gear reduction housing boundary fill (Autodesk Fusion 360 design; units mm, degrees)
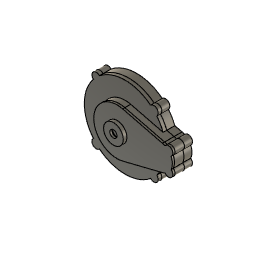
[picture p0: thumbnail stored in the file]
parameter "Drive_Gear_Dia" = 96 (= "( Drive_Gear_Teeth * Gear_Module ) * 1 mm")
parameter "Driven_Gear_Dia" = 32 (= "( Driven_Gear_Teeth * Gear_Module ) * 1 mm")
parameter "Idle_Gear_Dia" = 20 (= "( Idle_Gear_Teeth * Gear_Module ) * 1 mm")
parameter "Mount_Bolts" = 8
parameter "Mount_Bolt_Flange" = 12
parameter "Idle_Gear_Shaft" = 8
parameter "Gear_Clearance_Dia" = 8
parameter "Drive_Gear_Shaft" = 10
parameter "Idle_Gear_Thickness" = 21
parameter "Gear_Thickness" = 8
parameter "Housing_Wall_Thickness" = 3
parameter "Gear_Gap" = 5
sketch "Layout Sketch" plane through (0, 0, 0) normal (0, 1, 0) x axis (1, 0, 0)
  circle C1 centre (0, 0) radius 48
  circle C2 centre (0, 0) radius 16
  circle C3 centre (58, 0) radius 10
  circle C4 centre (22.6316, -12.7989) radius 10
  circle C5 centre (38, 0) radius 10
  point P1 (0, 0)
  point P2 (0, 0)
  point P3 (0, 0)
  point P4 (58, 0)
  coincident P1 P2
  concentric C1 C2
  horizontal P3 P4
  tangent C1 C3
  tangent C3 C5
  tangent C4 C5
  tangent C2 C4
  tangent C1 C5
  dimension "d12" diameter C1 = 96 (= "Drive_Gear_Dia")
  dimension "d13" diameter C2 = 32 (= "Driven_Gear_Dia")
  dimension "d14" diameter C3 = 20 (= "Idle_Gear_Dia")
  dimension "d15" diameter C4 = 20 (= "Idle_Gear_Dia")
  dimension "d16" diameter C5 = 20 (= "Idle_Gear_Dia")
sketch "Housing Layout Sketch" plane through (0, 0, 0) normal (0, 1, 0) x axis (1, 0, 0)
  line L1 (0, 56) -> (0, 0)
  line L2 (39.598, 39.598) -> (0, 0)
  line L3 (-56, 0) -> (0, 0)
  line L4 (70.7279, -12.7279) -> (58, 0)
  line L5 (62.3448, -17.4678) -> (7.7241, -31.0538)
  line L6 (62.3448, 17.4678) -> (7.7241, 31.0538)
  circle C1 centre (0, 0) radius 56
  circle C2 centre (0, 0) radius 48
  circle C3 centre (58, 0) radius 10
  circle C4 centre (58, 0) radius 18
  circle C5 centre (39.598, 39.598) radius 6
  circle C6 centre (-39.598, 39.598) radius 6
  circle C7 centre (-39.598, -39.598) radius 6
  circle C8 centre (39.598, -39.598) radius 6
  circle C9 centre (70.7279, -12.7279) radius 6
  circle C10 centre (70.7279, 12.7279) radius 6
  circle C11 centre (39.598, 39.598) radius 4
  circle C12 centre (-39.598, 39.598) radius 4
  circle C13 centre (-39.598, -39.598) radius 4
  circle C14 centre (39.598, -39.598) radius 4
  circle C15 centre (70.7279, -12.7279) radius 4
  circle C16 centre (70.7279, 12.7279) radius 4
  circle C17 centre (0, 0) radius 16
  circle C18 centre (22.6316, -12.7989) radius 10
  circle C19 centre (38, 0) radius 10
  circle C20 centre (0, 0) radius 32
  circle C21 centre (22.6316, -12.7989) radius 4
  circle C22 centre (38, 0) radius 4
  circle C23 centre (58, 0) radius 4
  circle C24 centre (0, 0) radius 52
  circle C25 centre (0, 0) radius 5
  point P1 (0, 0)
  point P2 (0, 0)
  point P6 (39.598, 39.598)
  point P7 (0, 0)
  point P8 (0, 56)
  point P3 (0, 0)
  point P9 (0, 0)
  point P10 (39.598, 39.598)
  point P11 (-56, 0)
  point P13 (-39.598, -39.598)
  point P14 (39.598, -39.598)
  point P15 (70.7279, -12.7279)
  point P4 (58, 0)
  point P16 (58, 0)
  point P17 (70.7279, -12.7279)
  point P29 (7.7241, -31.0538)
  point P30 (62.3448, -17.4678)
  point P31 (7.7241, 31.0538)
  point P32 (62.3448, 17.4678)
  point P35 (58, 0)
  coincident P1 P2
  coincident C1 P6
  coincident P2 P7
  coincident C1 P8
  vertical L1
  coincident P3 P9
  coincident C1 P10
  coincident P6 P10
  coincident C1 P11
  perpendicular L1 L3
  symmetric C5 L1 C6
  coincident C1 P13
  symmetric L3 C6 C7
  coincident C1 P14
  symmetric L1 C7 C8
  coincident C4 P15
  coincident P4 P16
  coincident P15 P17
  equal C5 C9
  symmetric L3 C9 C10
  concentric C5 C11
  concentric C6 C12
  concentric C7 C13
  concentric C8 C14
  concentric C9 C15
  concentric C10 C16
  equal C15 C16
  equal C14 C15
  equal C13 C14
  equal C12 C13
  equal C11 C12
  concentric C17 C20
  coincident C20 P29
  coincident C4 P30
  coincident C20 P31
  coincident C4 P32
  tangent C20 L5
  tangent C4 L5
  tangent C20 L6
  tangent C4 L6
  concentric C18 C21
  concentric C19 C22
  coincident P16 P35
  equal C22 C23
  equal C21 C22
  concentric C17 C24
  concentric C24 C25
  dimension "Gear_Clearance_Drive" distance C1 C2 = 8 (= "Gear_Clearance_Dia")
  dimension "d18" = 8 (= "Gear_Clearance_Dia")
  dimension "d19" diameter C5 = 12 (= "Mount_Bolt_Flange")
  dimension "d20" angle L1 L2 = 45
  dimension "d21" angle L1 L4 = 45
  dimension "d22" diameter C11 = 8 (= "Mount_Bolts")
  dimension "d23" distance C17 C20 = 16 (= "Gear_Clearance_Dia * 2")
  dimension "d24" diameter C23 = 8 (= "Idle_Gear_Shaft")
  dimension "d25" diameter C24 = 104 (= "Drive_Gear_Dia + Gear_Clearance_Dia")
  dimension "d27" diameter C25 = 10
work_plane "WorkPlane1" AlongDistance 11 (= "Gear_Thickness + Housing_Wall_Thickness")
work_plane "WorkPlane2"
work_plane "WorkPlane3"
extrude "Extrude1" new body sketch "Housing Layout Sketch" profile of C1 C4 C5 C6 C7 C8 C9 C10 C11 C12 C13 C14 C15 C16 C20 L5 L6 C21 C22 C23 C24 C25 to an object bodies "Back Housing"
extrude "Extrude2" new body of existing geometry to an object bodies "Front Housing"
extrude "Extrude3" sketch "Housing Layout Sketch" profile of C1 C4 C9 C10 C15 C16 C20 L5 L6 C21 C22 C23 C24 C25 to an object
extrude "Extrude4" new body of existing geometry blind 3 (= "Housing_Wall_Thickness") bodies "Front Cover"
combine "Combine1"
sketch "Front Cover Cut" plane through (0, -13, 0) normal (0, -1, 0) x axis (1, 0, 0)
  line L1 (7.7241, 31.0538) -> (62.3448, 17.4678)
  line L2 (62.3448, -17.4678) -> (7.7241, -31.0538)
  line L3 (62.3448, 17.4678) -> (7.7241, 31.0538)
  line L4 (62.3448, -17.4678) -> (7.7241, -31.0538)
  line L5 (7, 28.1425) -> (61.6207, 14.5565)
  line L6 (61.6207, -14.5565) -> (7, -28.1425)
  arc A1 centre (58, 0) radius 18 clockwise from (62.3448, 17.4678) to (65.8375, 16.2041)
  arc A2 centre (0, 0) radius 32 clockwise from (7.7241, -31.0538) to (7.7241, 31.0538)
  arc A3 centre (58, 0) radius 18 clockwise from (65.8375, -16.2041) to (62.3448, -17.4678)
  arc A4 centre (70.7279, -12.7279) radius 6 clockwise from (74.2041, -7.8375) to (65.8375, -16.2041)
  arc A5 centre (58, 0) radius 18 clockwise from (74.2041, 7.8375) to (74.2041, -7.8375)
  arc A6 centre (70.7279, 12.7279) radius 6 clockwise from (65.8375, 16.2041) to (74.2041, 7.8375)
  circle C1 centre (0, 0) radius 32
  circle C2 centre (58, 0) radius 18
  arc A7 centre (0, 0) radius 32 clockwise from (7.7241, -31.0538) to (7.7241, 31.0538)
  arc A8 centre (58, 0) radius 18 clockwise from (62.3448, 17.4678) to (62.3448, -17.4678)
  arc A9 centre (58, 0) radius 15 clockwise from (61.6207, 14.5565) to (61.6207, -14.5565)
  arc A10 centre (0, 0) radius 29 clockwise from (7, -28.1425) to (7, 28.1425)
  point P18 (7.7241, -31.0538)
  point P21 (7.7241, -31.0538)
  point P5 (7.7241, 31.0538)
  point P20 (7.7241, 31.0538)
  point P15 (62.3448, 17.4678)
  point P24 (62.3448, 17.4678)
  point P19 (62.3448, -17.4678)
  point P23 (62.3448, -17.4678)
  coincident P18 P21
  coincident P5 P20
  tangent L1 A7
  coincident P15 P24
  coincident P19 P23
  tangent L4 A8
extrude "Extrude5" cut sketch "Front Cover Cut" profile of A9 L5 L6 A10 to an object
sketch "Main Bearing OD" plane through (0, 0, 0) normal (0, 1, 0) x axis (1, 0, 0)
  circle C1 centre (0, 0) radius 10.5
  point P1 (0, 0)
  point P2 (0, 0)
  coincident P1 P2
  dimension "d47" diameter C1 = 21
extrude "Extrude6" cut sketch "Main Bearing OD" no distance stored
sketch "Front Cover Bearing" plane through (0, 0, 0) normal (1, 0, 0) x axis (0, 1, 0)
  line L1 (-16, -10.5) -> (-13, -10.5)
  line L2 (-13, 10.5) -> (-16, 10.5)
  line L3 (-18, 10.5) -> (-16, 10.5)
  line L4 (-18, 5) -> (-18, 10.5)
  line L5 (-21, 5) -> (-18, 5)
  line L6 (-21, 13.5) -> (-21, 5)
  line L7 (-16, 13.5) -> (-21, 13.5)
  line L8 (-16, 10.5) -> (-16, 13.5)
  line L9 (-21.9581, 0) -> (0, 0)
  point P4 (-16, 10.5)
  point P6 (-16, 10.5)
  point P12 (-16, 10.5)
  point P1 (0, 0)
  point P13 (0, 0)
  point P5 (-13, 10.5)
  point P8 (-18, 5)
  point P9 (-21, 5)
  point P11 (-16, 13.5)
  coincident P4 P6
  parallel L2 L3
  perpendicular L3 L4
  perpendicular L4 L5
  perpendicular L3 L6
  perpendicular L6 L7
  coincident P4 P12
  perpendicular L3 L8
  coincident P1 P13
  parallel L7 L9
  dimension "d49" distance P5 L4 = 5
  dimension "d50" distance P8 P9 = 3 (= "Housing_Wall_Thickness")
  dimension "d51" distance P11 P12 = 3 (= "d50")
  dimension "d52" = 10
revolve "Revolve1" sketch "Front Cover Bearing" AlongAngle 360
sketch "Sketch6" plane through (0, 11, 0) normal (0, 1, 0) x axis (-1, 0, 0)
  line L1 (-62.3448, 17.4678) -> (-52.3217, 19.9608)
  line L2 (-52.3217, -19.9608) -> (-62.3448, -17.4678)
  circle C1 centre (0, 0) radius 10.5
  arc A1 centre (0, 0) radius 56 clockwise from (-43.6072, -35.1341) to (-52.3217, -19.9608)
  arc A2 centre (-39.598, -39.598) radius 6 clockwise from (-35.1341, -43.6072) to (-43.6072, -35.1341)
  arc A3 centre (0, 0) radius 56 clockwise from (35.1341, -43.6072) to (-35.1341, -43.6072)
  arc A4 centre (39.598, -39.598) radius 6 clockwise from (43.6072, -35.1341) to (35.1341, -43.6072)
  arc A5 centre (0, 0) radius 56 clockwise from (43.6072, 35.1341) to (43.6072, -35.1341)
  arc A6 centre (39.598, 39.598) radius 6 clockwise from (35.1341, 43.6072) to (43.6072, 35.1341)
  arc A7 centre (0, 0) radius 56 clockwise from (-35.1341, 43.6072) to (35.1341, 43.6072)
  arc A8 centre (-39.598, 39.598) radius 6 clockwise from (-43.6072, 35.1341) to (-35.1341, 43.6072)
  arc A9 centre (0, 0) radius 56 clockwise from (-52.3217, 19.9608) to (-43.6072, 35.1341)
  arc A10 centre (-58, 0) radius 18 clockwise from (-65.8375, 16.2041) to (-62.3448, 17.4678)
  arc A11 centre (-70.7279, 12.7279) radius 6 clockwise from (-74.2041, 7.8375) to (-65.8375, 16.2041)
  arc A12 centre (-58, 0) radius 18 clockwise from (-74.2041, -7.8375) to (-74.2041, 7.8375)
  arc A13 centre (-70.7279, -12.7279) radius 6 clockwise from (-65.8375, -16.2041) to (-74.2041, -7.8375)
  arc A14 centre (-58, 0) radius 18 clockwise from (-62.3448, -17.4678) to (-65.8375, -16.2041)
  circle C2 centre (0, 0) radius 10.5
  circle C3 centre (0, 0) radius 13.5
  point P1 (0, 0)
  point P26 (0, 0)
  coincident P1 P26
  concentric C1 C3
  dimension "d54" diameter C2 = 21
  dimension "d55" distance C2 C3 = 3 (= "Housing_Wall_Thickness")
extrude "Extrude7" new body blind 2
work_plane "WorkPlane4" AlongDistance 2
named bodies: "Back Housing", "Front Housing", "Front Cover"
